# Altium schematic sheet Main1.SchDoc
size A4; SheetNumber: 2; SheetTotal: 3
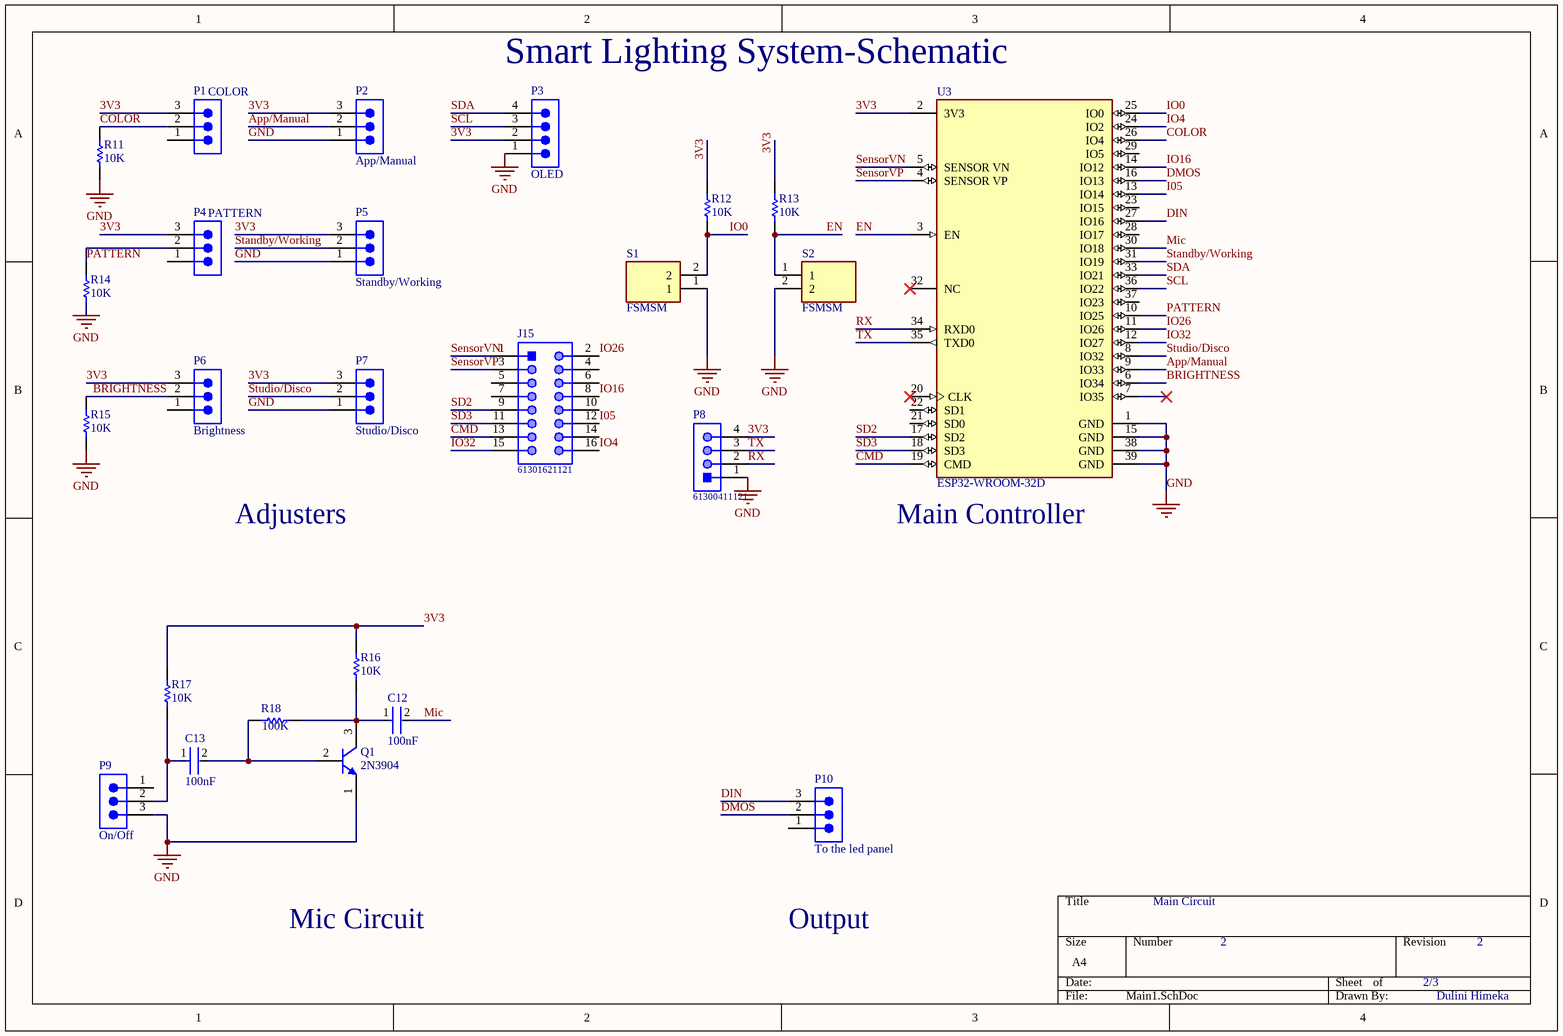
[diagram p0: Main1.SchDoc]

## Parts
C12  100nF  [FP-CL31-IPC_C]
C13  100nF  [FP-CL31-IPC_C]
J15  61301621121  [61301621121]
P1  COLOR  [SMTC-TSW-103-07-X-S]
P2  App/Manual  [SMTC-TSW-103-07-X-S]
P3  OLED  [SMTC-TSW-104-08-X-S]
P4  PATTERN  [SMTC-TSW-103-07-X-S]
P5  Standby/Working  [SMTC-TSW-103-07-X-S]
P6  Brightness  [SMTC-TSW-103-07-X-S]
P7  Studio/Disco  [SMTC-TSW-103-07-X-S]
P8  61300411121  [61300411121]
P9  On/Off  [SMTC-TSW-103-07-X-S]
P10  To the led panel  [SMTC-TSW-103-07-X-S]
Q1  2N3904  [ONSC-TO-92-3-29-11]
R11  10K  [RESC3116X65X40ML10T20]
R12  10K  [RESC3116X65X40ML10T20]
R13  10K  [RESC3116X65X40ML10T20]
R14  10K  [RESC3116X65X40ML10T20]
R15  10K  [RESC3116X65X40ML10T20]
R16  10K  [RESC3116X65X40ML10T20]
R17  10K  [RESC3116X65X40ML10T20]
R18  100K  [RESC3116X65X40ML10T20]
S1  FSMSM  [FSMSM]
S2  FSMSM  [FSMSM]
U3  ESP32-WROOM-32D  [FP-ESP32-WROOM-32D-MFG]

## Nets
GND: P2.1 P3.1 P5.1 P7.1 P8.1 P9.3 Q1.1(E) R11.1 R14.1 R15.1 S1.1 S2.2 U3.1(GND) U3.15(GND) U3.38(GND) U3.39(GND)
3V3: P1.3 P2.3 P3.2 P4.3 P5.3 P6.3 P7.3 P8.4 R12.2 R13.2 R16.2 R17.2 U3.2(3V3)
App/Manual: P2.2 U3.9(IO33)
BRIGHTNESS: P6.2 R15.2 U3.6(IO34)
CMD: J15.13 U3.19(CMD)
COLOR: P1.2 R11.2 U3.26(IO4)
DIN: P10.3 U3.27(IO16)
DMOS: P10.2 U3.16(IO13)
EN: R13.1 S2.1 U3.3(EN)
I05: J15.12 U3.13(IO14)
IO0: R12.1 S1.2 U3.25(IO0)
IO4: J15.16 U3.24(IO2)
IO16: J15.8 U3.14(IO12)
IO26: J15.2 U3.11(IO26)
IO32: J15.15 U3.12(IO27)
Mic: C12.2 U3.30(IO18)
PATTERN: P4.2 R14.2 U3.10(IO25)
RX: P8.2 U3.34(RXD0)
SCL: P3.3 U3.36(IO22)
SD2: J15.9 U3.17(SD2)
SD3: J15.11 U3.18(SD3)
SDA: P3.4 U3.33(IO21)
SensorVN: J15.1 U3.5(SENSOR_VN)
SensorVP: J15.3 U3.4(SENSOR_VP)
Standby/Working: P5.2 U3.31(IO19)
Studio/Disco: P7.2 U3.8(IO32)
TX: P8.3 U3.35(TXD0)
NetC12_1: C12.1 Q1.3(C) R16.1 R18.2
NetC13_1: C13.1 P9.2 R17.1
NetC13_2: C13.2 Q1.2(B) R18.1

Not connected (* = marked no-connect by the designer): J15 4 5 6 7 10 14; P1 1; P4 1; P6 1; P9 1; P10 1; U3 7(IO35)* 20(CLK)* 21(SD0) 22(SD1) 23(IO15) 28(IO17) 29(IO5) 32(NC)* 37(IO23)

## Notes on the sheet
- Smart Lighting System-Schematic
- Adjusters
- (near U3) Main Controller
- Main Circuit
- Mic Circuit
- Output
- 2
- 2/3
- Dulini Himeka

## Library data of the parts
C12 C13 = CMP-13271-001514-1: Cap Ceramic 100nF 100V X7R ±10% SMD 1206 +125°C Embossed T/R
J15 = CMP-1502-01097-1: THT Vertical Pin Header WR-PHD, Pitch 2.54 mm, Dual Row, 16 pins; Manufacturer: Wurth Elektronik; Gender: Male; Rated Current: 3A; Pitch: 2.54mm; Withstanding Voltage: 500VAC; Contact Resistance: 20mOhm; Working Voltage: 250VAC; Pin Number: 16
P1 P2 P4-P7 P9 P10 = CMP-1024-00331-1: 0.025" SQ Post Header, Through-hole, Vertical, -55 to 125 degC, 2.54 mm Pitch, 3-Pin, Male, RoHS; Manufacturer: Samtec; PartNumber: TSW-103-07-F-S; Pitch: 2.54 mm
P3 = CMP-1024-00357-1: 0.025" SQ Post Header, Through-hole, Vertical, -55 to 125 degC, 2.54 mm Pitch, 4-Pin, Male, RoHS; Manufacturer: Samtec; PartNumber: TSW-104-08-G-S; Pitch: 2.54 mm
P8 = CMP-1502-01064-1: THT Vertical Pin Header WR-PHD, Pitch 2.54 mm, Single Row, 4 pins; Manufacturer: Wurth Elektronik; Withstanding Voltage: 500VAC; Rated Current: 3A; Working Voltage: 250VAC; Pin Number: 4; Gender: Male; Contact Resistance: 20mOhm; Pitch: 2.54mm
Q1 = CMP-2000-05562-1: General Purpose Transistor, NPN Silicon, 200 mA, 60 V, -55 to 150 degC, 3-Pin TO-92, RoHS, Bulk; Manufacturer: ONSemiconductor; Emitter- Base Voltage VEBO: 6V; Maximum Power Dissipation: 625mW; Maximum DC Collector Current: 0.2A; Collector- Emitter Voltage VCEO Max: 40V; Collector- Base Voltage VCBO: 60V; DC Collector/Base Gain hfe Min: 60; Configuration: Single; Collector-Emitter Saturation Voltage: 0.3V; Gain Bandwidth Product fT: 270MHz
R11-R17 = CMP-1014-00623-2: Chip Resistor, 10 KOhm, +/- 1%, 0.25 W, -55 to 155 degC, 1206 (3216 Metric), RoHS, Tape and Reel; Manufacturer: Yageo; Voltage Rating: 200V; Resistance: 10KOhm; Temperature Coefficient: 100ppm/degreesC; Power Rating: 250mW
R18 = CMP-2100-03674-1: Chip Resistor, 100 KOhm, +/- 1%, 0.25 W, -55 to 155 degC, 1206 (3216 Metric), RoHS, Tape and Reel; Manufacturer: Yageo; Voltage Rating: 200V; Temperature Coefficient: 100ppm/degreesC; Power Rating: 250mW
S1 S2 = FSMSM: Switch; Manufacturer_Name: TE Connectivity
U3 = CMP-194065-000003-1: WIFI MODULE 32MBITS SPI FLASH; Manufacturer: Espressif Systems; Max Supply Voltage: 3.6V; Nominal Supply Current: 500mA; Max Frequency: 2484MHz; Number Of Adc Channels: 16; Number Of Gpio: 32; Interface: I2C,SPI,UART,Ethernet,I2S,Other; Data Rate: 150Mbits/s; Min Supply Voltage: 3V; Bandwidth: 72MHz; Sensitivity: -98dBm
